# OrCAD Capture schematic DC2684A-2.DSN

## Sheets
1 PAGE2: size C; title: IEEE 802.3bt 8-CHANNEL PSE DAUGHTER CARD; rev: 2; company: TM
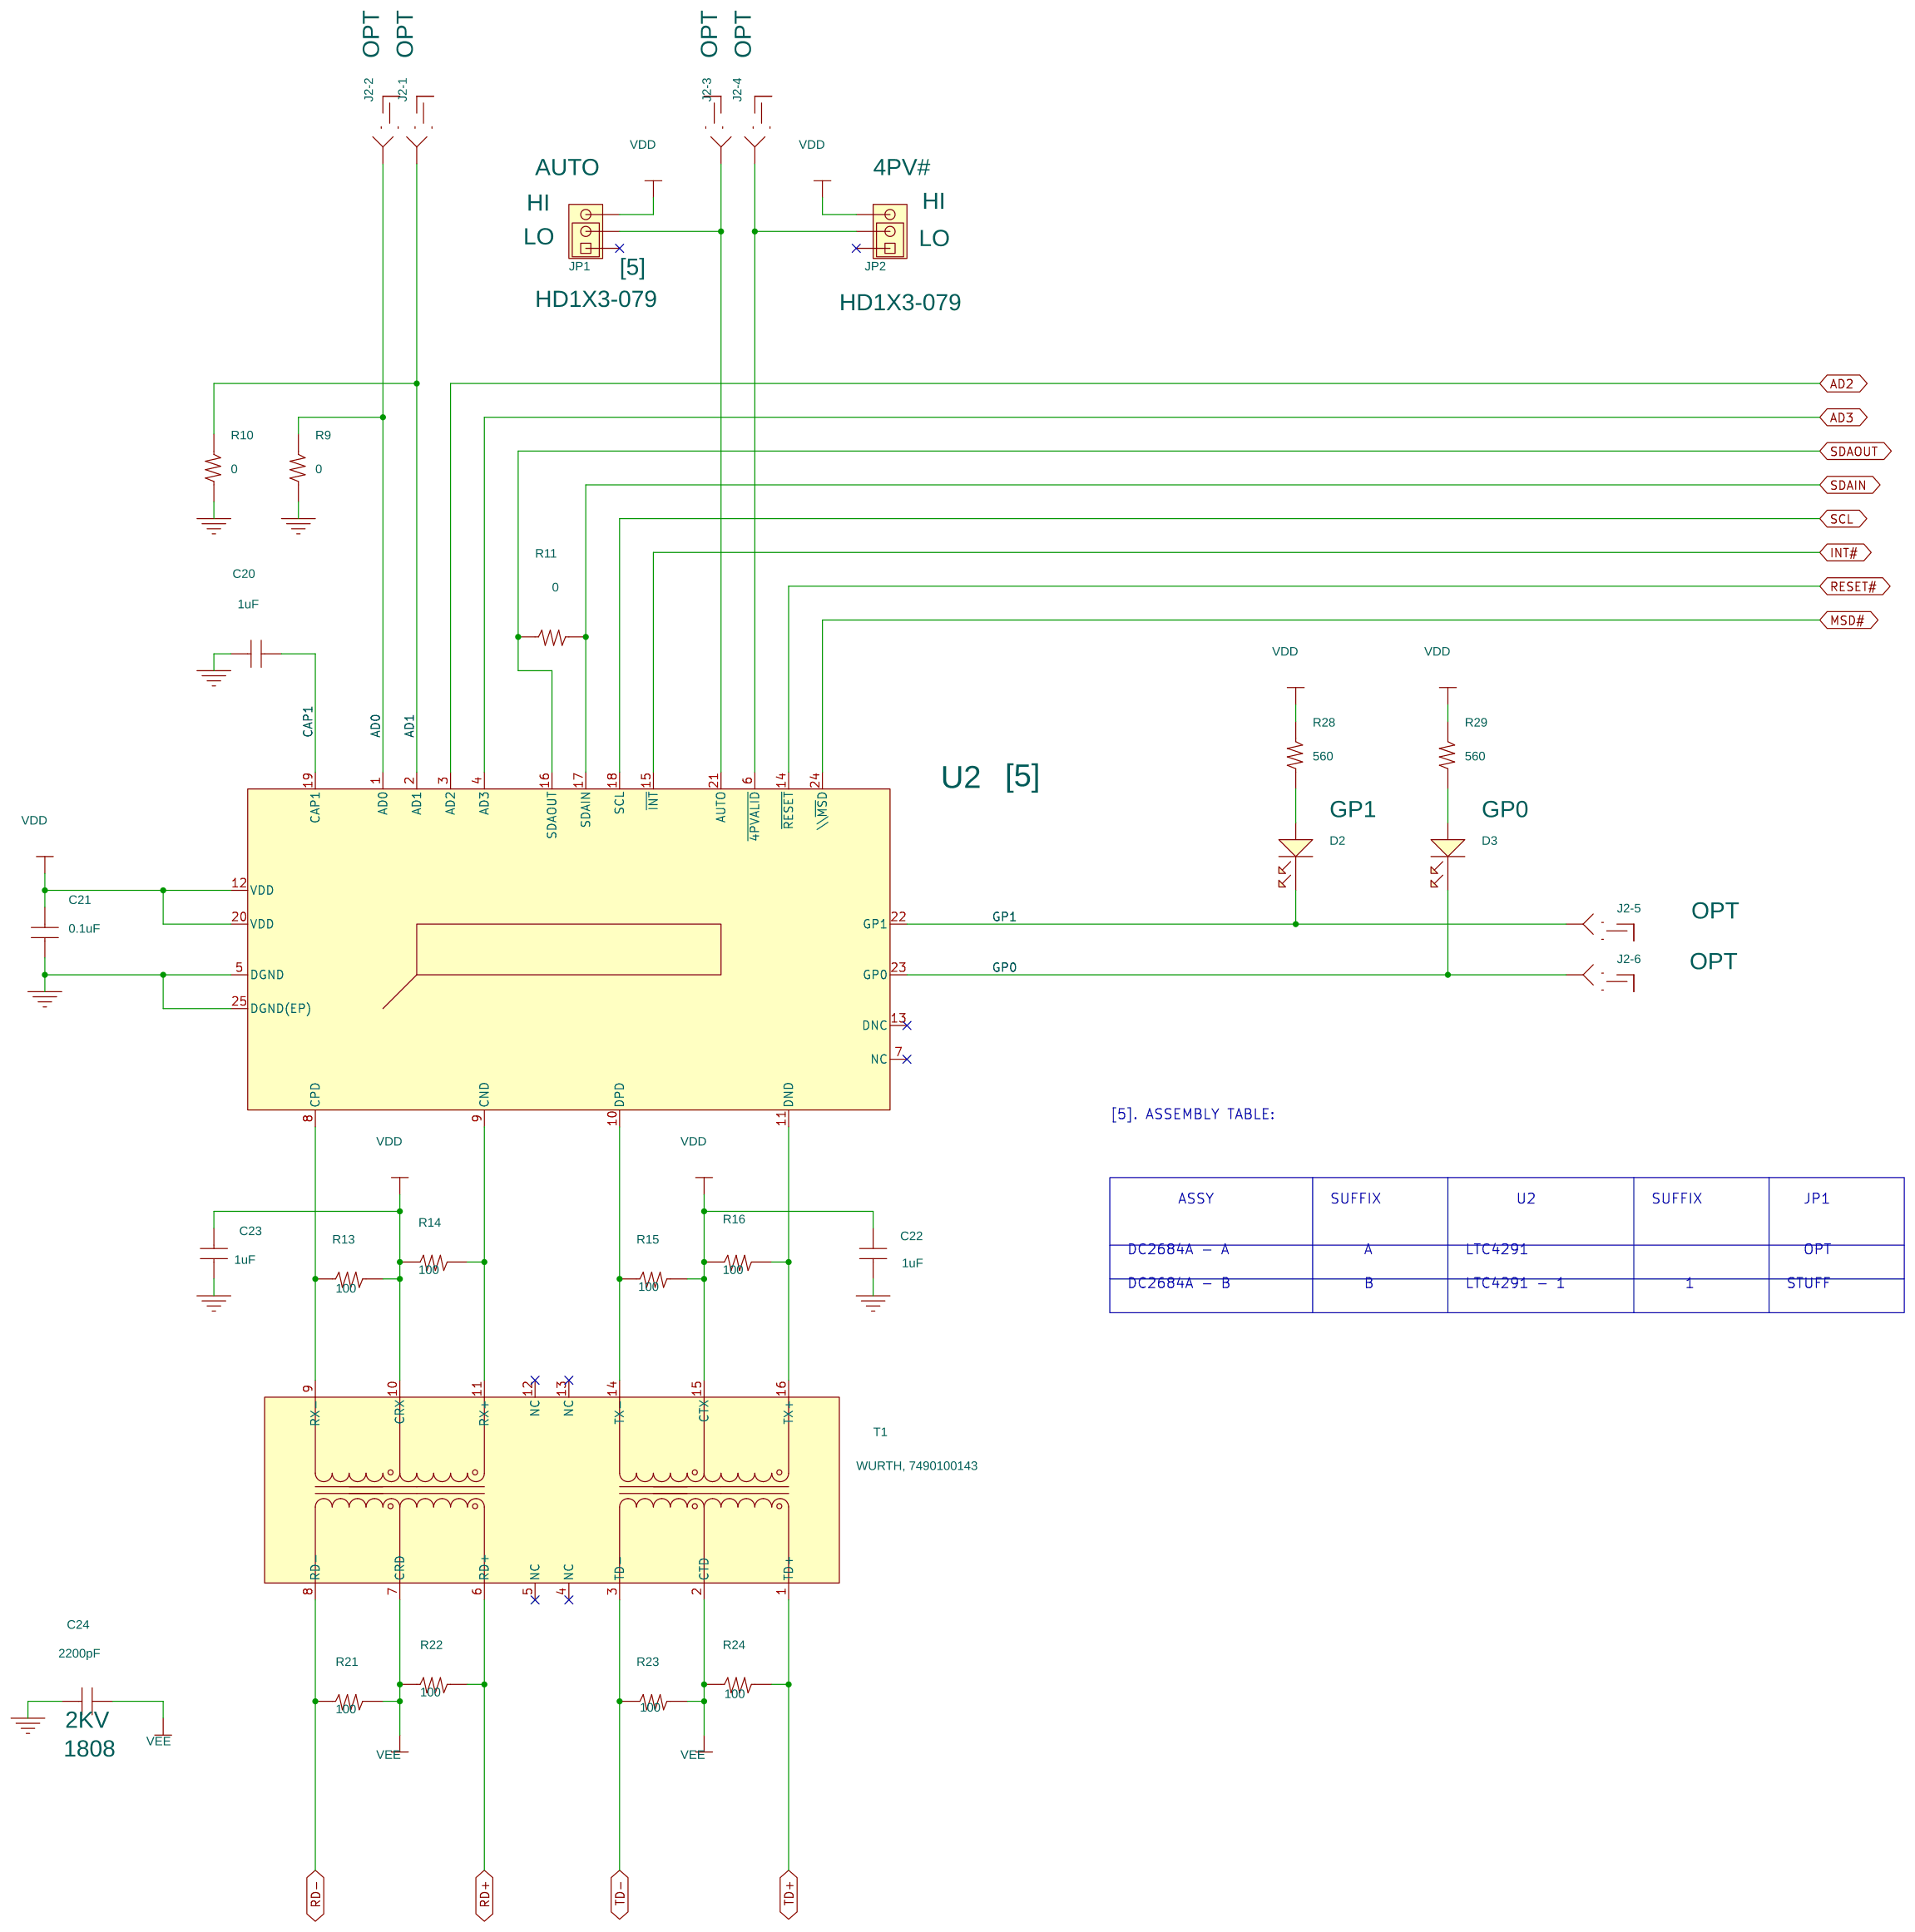
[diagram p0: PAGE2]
2 PAGE1: size Custom
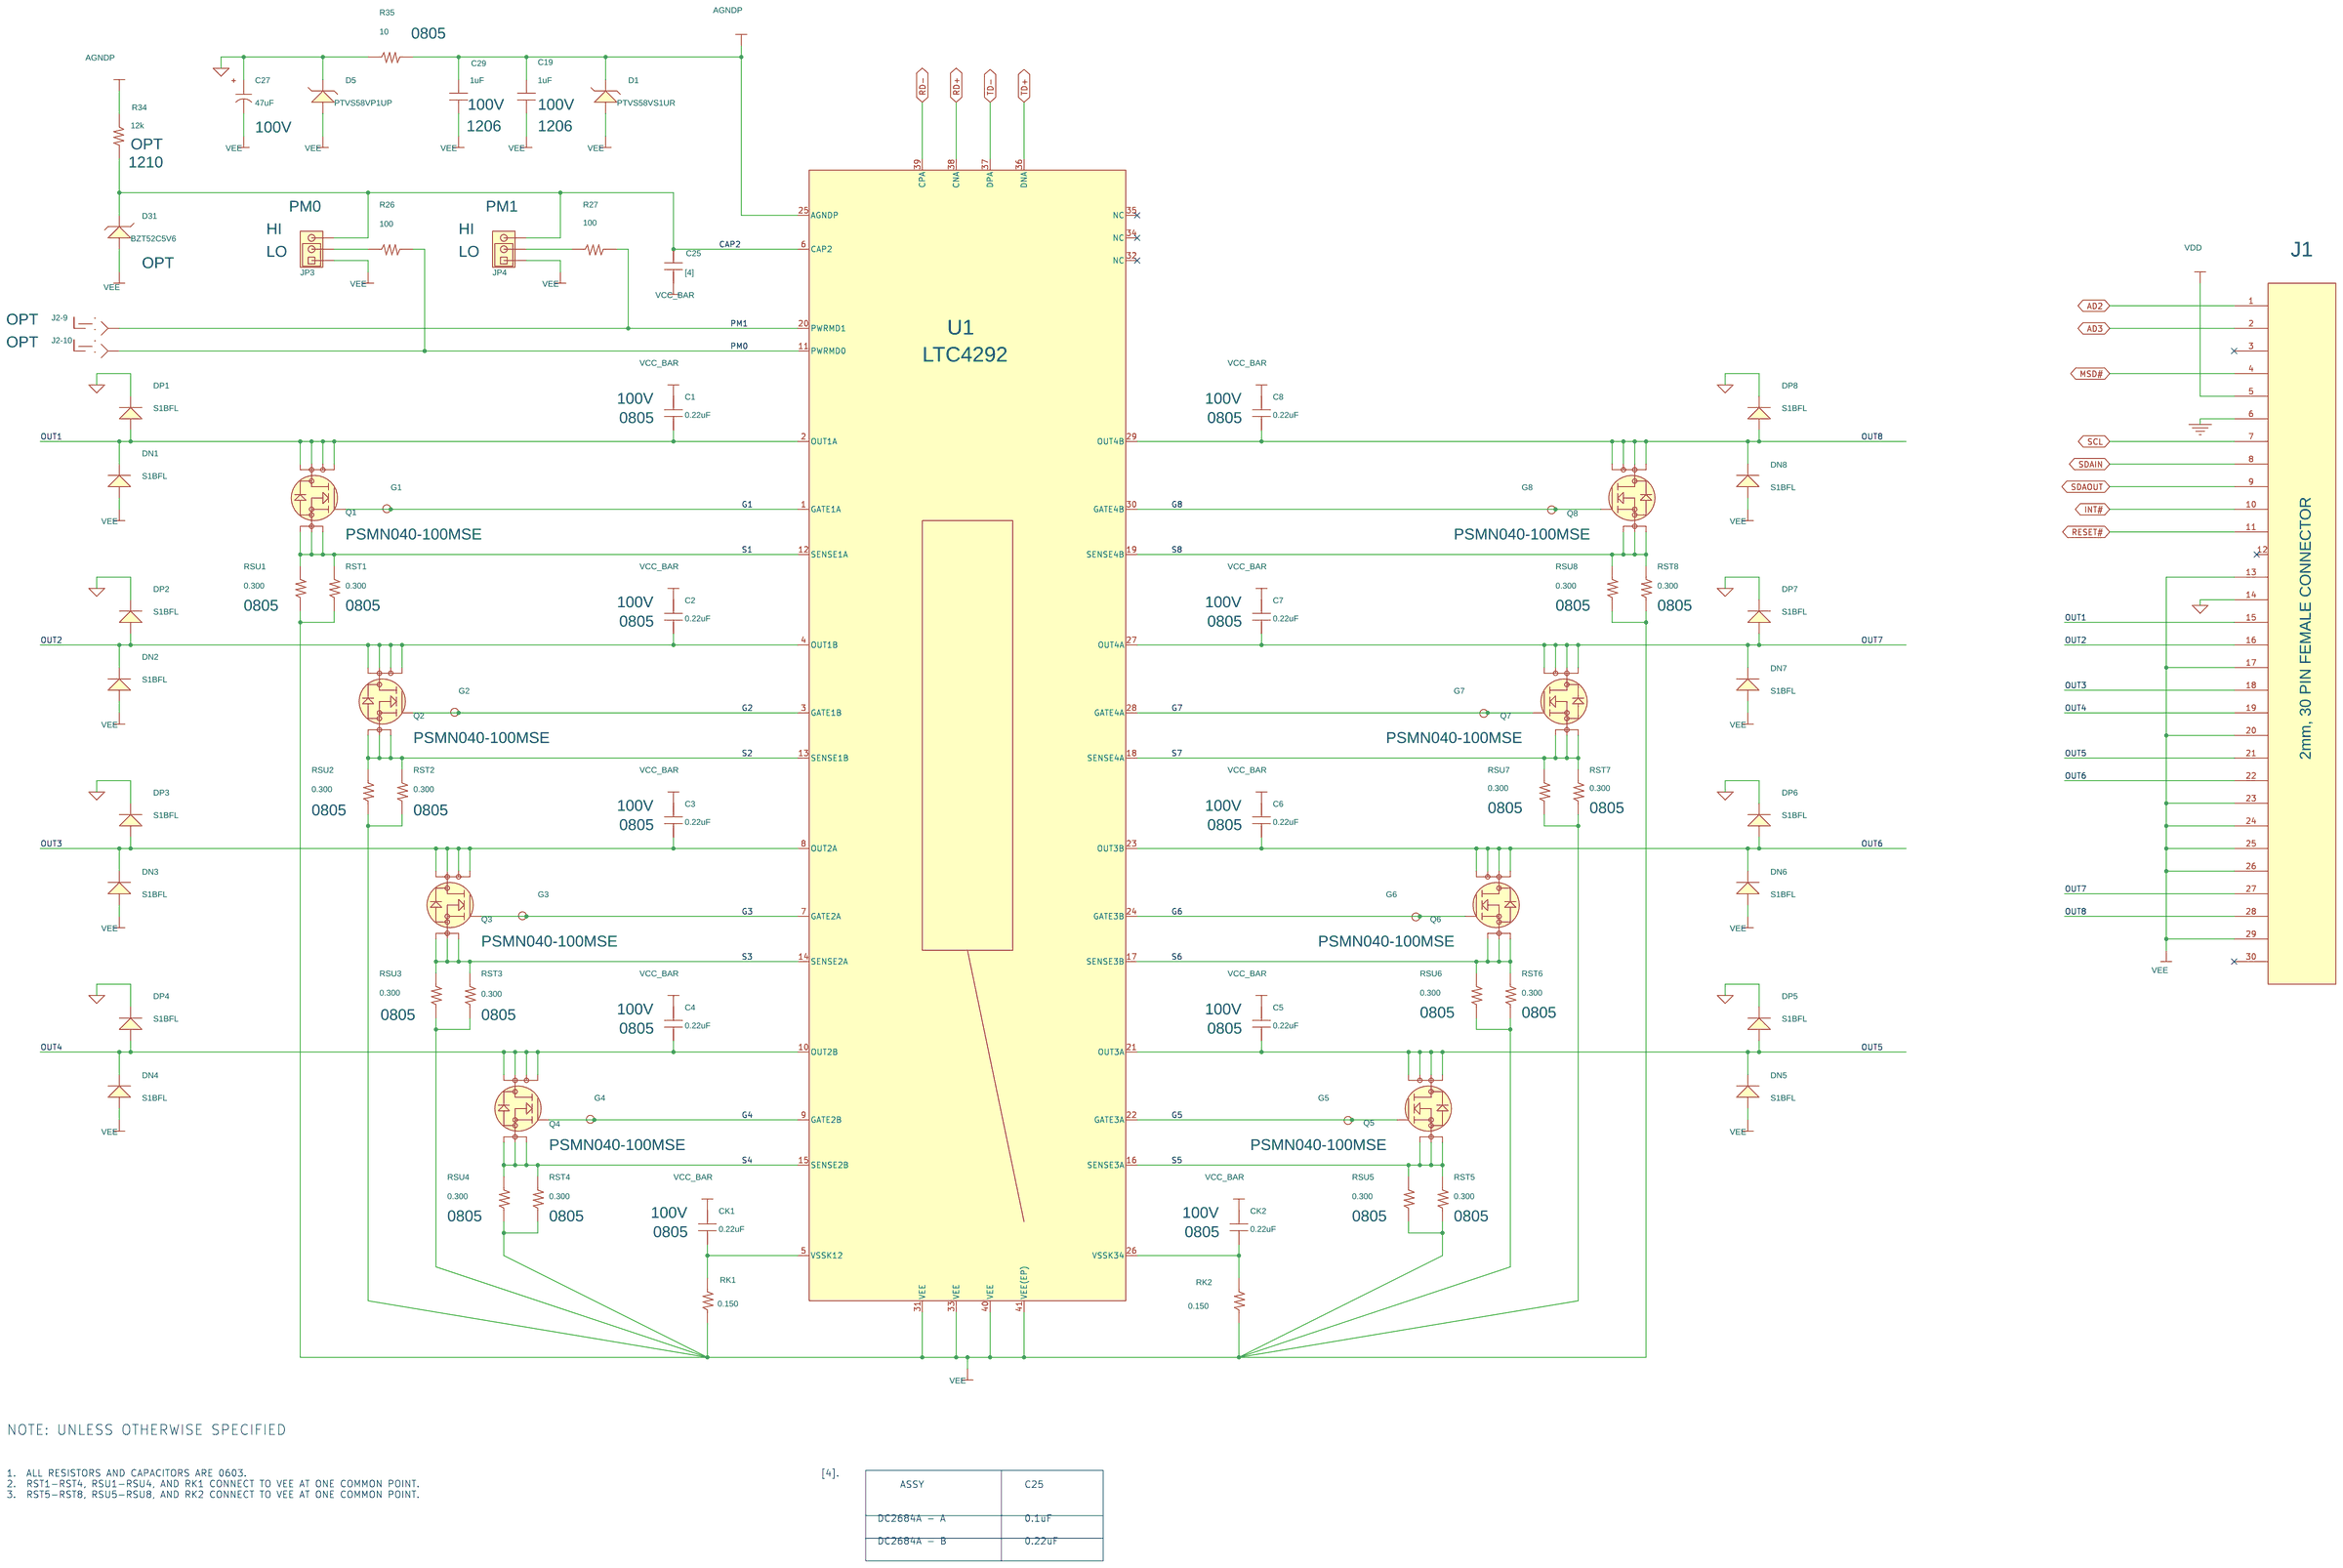
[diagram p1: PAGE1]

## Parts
sheet PAGE1
C1  0.22uF  [0805]
C2  0.22uF  [0805]
C3  0.22uF  [0805]
C4  0.22uF  [0805]
C5  0.22uF  [0805]
C6  0.22uF  [0805]
C7  0.22uF  [0805]
C8  0.22uF  [0805]
C19  1uF  [1206]
C25  [4]  [0603]
C27  47uF  [C-NICHICON-UVK-8X11.5]
C29  1uF  [1206]
CK1  0.22uF  [0805]
CK2  0.22uF  [0805]
D1  PTVS58VS1UR  [SOD123W]
D5  PTVS58VP1UP  [SOD128]
D31  BZT52C5V6  [SOD123]
DN1  S1BFL  [SOD123]
DN2  S1BFL  [SOD123]
DN3  S1BFL  [SOD123]
DN4  S1BFL  [SOD123]
DN5  S1BFL  [SOD123]
DN6  S1BFL  [SOD123]
DN7  S1BFL  [SOD123]
DN8  S1BFL  [SOD123]
DP1  S1BFL  [SOD123]
DP2  S1BFL  [SOD123]
DP3  S1BFL  [SOD123]
DP4  S1BFL  [SOD123]
DP5  S1BFL  [SOD123]
DP6  S1BFL  [SOD123]
DP7  S1BFL  [SOD123]
DP8  S1BFL  [SOD123]
G1  PAD060-SMT-T  [PAD060-SMT-T]
G2  PAD060-SMT-T  [PAD060-SMT-T]
G3  PAD060-SMT-T  [PAD060-SMT-T]
G4  PAD060-SMT-T  [PAD060-SMT-T]
G5  PAD060-SMT-T  [PAD060-SMT-T]
G6  PAD060-SMT-T  [PAD060-SMT-T]
G7  PAD060-SMT-T  [PAD060-SMT-T]
G8  PAD060-SMT-T  [PAD060-SMT-T]
J1  HD1X30-079-RA  [HD1X30-079-RA]
JP3  HD1X3-079  [HD1X3-079]
JP4  HD1X3-079  [HD1X3-079]
Q1  PSMN040-100MSE  [LFPAK33-8PIN]
Q2  PSMN040-100MSE  [LFPAK33-8PIN]
Q3  PSMN040-100MSE  [LFPAK33-8PIN]
Q4  PSMN040-100MSE  [LFPAK33-8PIN]
Q5  PSMN040-100MSE  [LFPAK33-8PIN]
Q6  PSMN040-100MSE  [LFPAK33-8PIN]
Q7  PSMN040-100MSE  [LFPAK33-8PIN]
Q8  PSMN040-100MSE  [LFPAK33-8PIN]
R26  100  [0603]
R27  100  [0603]
R34  12k  [1210]
R35  10  [0805]
RK1  0.150  [0603]
RK2  0.150  [0603]
RST1  0.300  [0805]
RST2  0.300  [0805]
RST3  0.300  [0805]
RST4  0.300  [0805]
RST5  0.300  [0805]
RST6  0.300  [0805]
RST7  0.300  [0805]
RST8  0.300  [0805]
RSU1  0.300  [0805]
RSU2  0.300  [0805]
RSU3  0.300  [0805]
RSU4  0.300  [0805]
RSU5  0.300  [0805]
RSU6  0.300  [0805]
RSU7  0.300  [0805]
RSU8  0.300  [0805]
U1  Quad PSE Power Controller  [QFN40UJ-6X6]
sheet PAGE2
C20  1uF  [0603]
C21  0.1uF  [0603]
C22  1uF  [0603]
C23  1uF  [0603]
C24  2200pF  [1808]
D2  SML-012P8T  [LED-LTST-C190KGKT]
D3  SML-012P8T  [LED-LTST-C190KGKT]
J2  CON-2X5-ED-2MM  [CON-2X5-ED-2MM]  (sections -1,-10,-2,-3,-4,-5,-6,-9)
JP1  [5]  [HD1X3-079]
JP2  HD1X3-079  [HD1X3-079]
R9  0  [0603]
R10  0  [0603]
R11  0  [0603]
R13  100  [0603]
R14  100  [0603]
R15  100  [0603]
R16  100  [0603]
R21  100  [0603]
R22  100  [0603]
R23  100  [0603]
R24  100  [0603]
R28  560  [0603]
R29  560  [0603]
T1  WURTH, 7490100143  [TRANS-WE-7490100143]
U2  [5]  [QFN24UF-4X4]

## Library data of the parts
C1-C8 CK1 CK2 = CAP-NP: CAP SMD 0805 0.22uF 10% 100V X7R; Part Number: AVX 08051C224KAT2A; VOLTAGE: 100V
C19 = CAP-NP: VOLTAGE: 100V
C20-C23 C25 = CAP-NP
C27 = CAP: VOLTAGE: 100V
C29 = CAP-NP: 1ST PART FIELD: <1ST PART FIELD>; 2ND PART FIELD: <2ND PART FIELD>; VOLTAGE: 100V
D1 = DIODE-PTVS58VS1UR-SOD123W
D5 = DIODE-PTVS58VP1UP-SOD128
D31 = DIODE-BZT52C5V6-SOD123: OPT: OPT
DN1-DN8 DP1-DP8 = DIODE-MSE1PB-MICROSMP: 4TH PART FIELD: VISHAY; 5TH PART FIELD: MSE1PB, MSE1PD, MSE1PG, MSE1PJ
G1-G8 = E-SMT-060: TEXT: GP2
J1 = HD1X30-079-RA_0: 1ST PART FIELD: PIN 12 GOT CLIPPED BEFORE INSTALLED; 4th Part Field: 2mm, 30 PIN FEMALE CONNECTOR
JP3 = HD1X3: 1ST PART FIELD: PM0; 2ND PART FIELD: HI; 3RD PART FIELD: LO
JP4 = HD1X3: 1ST PART FIELD: PM1; 2ND PART FIELD: HI; 3RD PART FIELD: LO
Q1-Q8 = MOSFET_N-DIODE-PSMN040-LFPAK33: XSTR, MOSFET, N-CH, 40mOhm, 100V
R9-R11 R13-R16 R21-R24 R26-R29 R35 RK1 RK2 RST1-RST8 RSU1-RSU8 = R
R34 = R: OPT: OPT; VOLTAGE: 1/4W
U1 = LTC4292IUJ-QFN40UJ-6X6: 5th Part Field: LTC4292
C24 = CAP-NP: VOLTAGE: 2KV
D2 = LED-ROHM-SML-012P8TT86-GREEN: 1ST PART FIELD: GP1
D3 = LED-ROHM-SML-012P8TT86-GREEN: 1ST PART FIELD: GP0
J2 = CON-EDGE-2X5-079-TB: OPT: OPT
JP1 = HD1X3: 1ST PART FIELD: AUTO; 2ND PART FIELD: HI; 3RD PART FIELD: LO
JP2 = HD1X3: 1ST PART FIELD: 4PV#; 2ND PART FIELD: HI; 3RD PART FIELD: LO
T1 = TRANS-7490100143: Pin Names Visible: <Pin Names Visible>
U2 = LTC4291IUF-QFN24UF-4X4: 5th Part Field: <5th Part Field>

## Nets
Agnd: C27.1 D5.1 DP1.1 DP2.1 DP3.1 DP4.1 DP5.1 DP6.1 DP7.1 DP8.1 J1.14 R35.1
AGNDP: C1.1 C2.1 C3.1 C4.1 C5.1 C6.1 C7.1 C8.1 C19.1 C29.2 CK1.1 CK2.1 D1.1 R34.1 R35.2 U1.25(AGNDP)
GND: C20.2 C21.2 C22.1 C23.1 C24.2 J1.6 R9.2 R10.2 U2.5(DGND) U2.25(DGND(EP))
VDD: C21.1 C22.2 C23.2 J1.5 JP1.3 JP2.3 R13.2 R14.1 R15.2 R16.1 R28.1 R29.1 T1.10(CRX) T1.15(CTX) U2.12(VDD) U2.20(VDD)
VEE: C19.2 C24.1 C25.2 C27.2 C29.1 D1.2 D5.2 D31.2 DN1.2 DN2.2 DN3.2 DN4.2 DN5.2 DN6.2 DN7.2 DN8.2 J1.13 J1.17 J1.20 J1.23 J1.24 J1.25 J1.26 J1.29 JP3.1 JP4.1 R21.2 R22.1 R23.2 R24.1 RK1.1 RK2.1 RST1.1 RST2.1 RST3.1 RST4.1 RST5.1 RST6.1 RST7.1 RST8.1 RSU1.1 RSU2.1 RSU3.1 RSU4.1 RSU5.1 RSU6.1 RSU7.1 RSU8.1 T1.2(CTD) T1.7(CRD) U1.31(VEE) U1.33(VEE) U1.40(VEE) U1.41(VEE(EP))
AD0: J2.2(12) R9.1 U2.1(AD0)
AD1: J2.1(12) R10.1 U2.2(AD1)
AD2: J1.1 U2.3(AD2)
AD3: J1.2 U2.4(AD3)
CAP1: C20.1 U2.19(CAP1)
CAP2: C25.1 D31.1 JP3.3 JP4.3 R34.2 U1.6(CAP2)
G1: G1.1 Q1.4 U1.1(GATE1A)
G2: G2.1 Q2.4 U1.3(GATE1B)
G3: G3.1 Q3.4 U1.7(GATE2A)
G4: G4.1 Q4.4 U1.9(GATE2B)
G5: G5.1 Q5.4 U1.22(GATE3A)
G6: G6.1 Q6.4 U1.24(GATE3B)
G7: G7.1 Q7.4 U1.28(GATE4A)
G8: G8.1 Q8.4 U1.30(GATE4B)
GP0: D3.2 J2.6(12) U2.23(GP0)
GP1: D2.2 J2.5(12) U2.22(GP1)
INT#: J1.10 U2.15(~{INT})
MSD#: J1.4 U2.24(\\~{MS}D)
OUT1: C1.2 DN1.1 DP1.2 J1.15 Q1.5 Q1.6 Q1.7 Q1.8 U1.2(OUT1A)
OUT2: C2.2 DN2.1 DP2.2 J1.16 Q2.5 Q2.6 Q2.7 Q2.8 U1.4(OUT1B)
OUT3: C3.2 DN3.1 DP3.2 J1.18 Q3.5 Q3.6 Q3.7 Q3.8 U1.8(OUT2A)
OUT4: C4.2 DN4.1 DP4.2 J1.19 Q4.5 Q4.6 Q4.7 Q4.8 U1.10(OUT2B)
OUT5: C5.2 DN5.1 DP5.2 J1.21 Q5.5 Q5.6 Q5.7 Q5.8 U1.21(OUT3A)
OUT6: C6.2 DN6.1 DP6.2 J1.22 Q6.5 Q6.6 Q6.7 Q6.8 U1.23(OUT3B)
OUT7: C7.2 DN7.1 DP7.2 J1.27 Q7.5 Q7.6 Q7.7 Q7.8 U1.27(OUT4A)
OUT8: C8.2 DN8.1 DP8.2 J1.28 Q8.5 Q8.6 Q8.7 Q8.8 U1.29(OUT4B)
PM0: J2.10(12) R26.2 U1.11(PWRMD0)
PM1: J2.9(12) R27.2 U1.20(PWRMD1)
RD+: R22.2 T1.6(RD+) U1.38(CNA)
RD-: R21.1 T1.8(RD-) U1.39(CPA)
RESET#: J1.11 U2.14(~{RESET})
S1: Q1.1 Q1.2 Q1.3 RST1.2 RSU1.2 U1.12(SENSE1A)
S2: Q2.1 Q2.2 Q2.3 RST2.2 RSU2.2 U1.13(SENSE1B)
S3: Q3.1 Q3.2 Q3.3 RST3.2 RSU3.2 U1.14(SENSE2A)
S4: Q4.1 Q4.2 Q4.3 RST4.2 RSU4.2 U1.15(SENSE2B)
S5: Q5.1 Q5.2 Q5.3 RST5.2 RSU5.2 U1.16(SENSE3A)
S6: Q6.1 Q6.2 Q6.3 RST6.2 RSU6.2 U1.17(SENSE3B)
S7: Q7.1 Q7.2 Q7.3 RST7.2 RSU7.2 U1.18(SENSE4A)
S8: Q8.1 Q8.2 Q8.3 RST8.2 RSU8.2 U1.19(SENSE4B)
SCL: J1.7 U2.18(SCL)
SDAIN: J1.8 R11.2 U2.17(SDAIN)
SDAOUT: J1.9 R11.1 U2.16(SDAOUT)
TD+: R24.2 T1.1(TD+) U1.36(DNA)
TD-: R23.1 T1.3(TD-) U1.37(DPA)
N18854557: CK1.2 RK1.2 U1.5(VSSK12)
N18854961: CK2.2 RK2.2 U1.26(VSSK34)
N18872385: JP4.2 R27.1
N18927655: J2.4(12) JP2.2 U2.6(~{4PVALID})
N18927657: J2.3(12) JP1.2 U2.21(AUTO)
N18927760: R14.2 T1.11(RX+) U2.9(CND)
N18927762: R13.1 T1.9(RX-) U2.8(CPD)
N18927804: R15.1 T1.14(TX-) U2.10(DPD)
N18927806: R16.2 T1.16(TX+) U2.11(DND)
N18965900: D3.1 R29.2
N19011808: JP3.2 R26.1
N19084409: D2.1 R28.2

Not connected (* = marked no-connect by the designer): J1 3* 12* 30*; JP1 1*; JP2 1*; T1 4(NC)* 5(NC)* 12(NC)* 13(NC)*; U1 32(NC)* 34(NC)* 35(NC)*; U2 7(NC)* 13(DNC)*

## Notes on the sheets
sheet 1
- [5]. ASSEMBLY TABLE:
- ASSY
- SUFFIX
- U2
- SUFFIX
- JP1
- DC2684A - A
- A
- LTC4291
- OPT
- DC2684A - B
- B
- LTC4291 - 1
- 1
- STUFF
sheet 2
- NOTE: UNLESS OTHERWISE SPECIFIED
- 1.  ALL RESISTORS AND CAPACITORS ARE 0603.
  2.  RST1-RST4, RSU1-RSU4, AND RK1 CONNECT TO VEE AT ONE COMMON POINT.
  3.  RST5-RST8, RSU5-RSU8, AND RK2 CONNECT TO VEE AT ONE COMMON POINT.
- [4].
- ASSY
- C25
- DC2684A - A
- 0.1uF
- DC2684A - B
- 0.22uF
